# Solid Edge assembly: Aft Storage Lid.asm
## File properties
Author: m_hel
Template: Iso Metric Assembly.asm
Last saved by: m_hel
Revision: 11
Application: Solid Edge
Username: m_hel
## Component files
Aft Storage Lid.par
Lid Handle.asm
Lid Hinge.asm
Lid Hinge_mir.asm
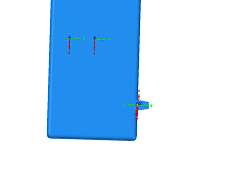
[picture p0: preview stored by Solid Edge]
